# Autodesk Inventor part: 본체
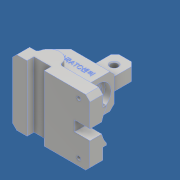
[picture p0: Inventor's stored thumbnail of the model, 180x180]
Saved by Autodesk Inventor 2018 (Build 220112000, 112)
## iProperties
Created: 2022-08
Part Number: 본체
Material: 알루미늄 6061
Document SubType Name: Modeling
Designer: home
Density: 2.7 g/cm^3
Appearance: 알루미늄 - 평지
Mass: 499.241 g
Surface Area: 337.564 cm^2
Volume: 184.904 cm^3
Author: home
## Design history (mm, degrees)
sketch "스케치1"
  geometry: L1 (63, 0)-(63, 15); L2 (-27, 15)-(-27, 0); L3 (63, 15)-(13, 15); L4 (-13, 15)-(-27, 15); L5 (10, 0)-(10, 8); L6 (10, 8)-(-10, 8); L7 (-10, 8)-(-10, 0); L8 (-27, 0)-(-10, 0); L9 (10, 0)-(63, 0); A1 r 13 centre (0, 15) between (13, 15) and (-13, 15); 2 further points
  constraints: 18 end point, 8 parallel, 2 horizontal, 2 perpendicular, 2 point on circle, 2 vertical alignment, 1 centre point, 1 midpoint
  dimensions: "d0" = 15 distance of L2.start L2.end; "d1" = 27 distance from line of L2 point (0, 0); "d2" = 90 distance of L2.end L1.start; "d3" = 26 diameter of A1; "d4" = 8 distance of L6.end L7.end; "d5" = 20 distance of L5.end L6.end; "d6" = 53 distance between parallel lines of L1 L5; "d7" = 15 distance between parallel lines of L3 L9; "d8" = 15 distance from line of point (0, 0) L3; "d9" = 50 distance from line of L3.end L1
extrude "돌출1" new body sketch "스케치1" stored distance "d10" = 76; taper "d11" = 0 deg
sketch "스케치2"
  geometry: L1 (-27, 0)-(-27, 15) reference; L2 (-27, 15)-(-13, 15) reference; L3 (13, 15)-(63, 15) reference; L4 (63, 15)-(63, 0) reference; L5 (63, 0)-(10, 0) reference; L6 (10, 0)-(10, 8) reference; L7 (10, 8)-(-10, 8) reference; L8 (-10, 8)-(-10, 0) reference; L9 (-10, 0)-(-27, 0) reference; L10 (-27, 0)-(-27, 15) reference; L11 (-27, 15)-(31, 15); L12 (31, 15)-(31, 60); L13 (31, 60)-(-27, 60); L14 (-27, 60)-(-27, 15); L15 (13, 15)-(63, 15) reference; L16 (63, 15)-(31, 15); L17 (31, 15)-(31, 19); L18 (31, 19)-(63, 19); L19 (63, 19)-(63, 15); A1 r 13 centre (0, 15) between (13, 15) and (-13, 15) reference; 1 further point
  constraints: 16 end point, 3 parallel, 2 horizontal, 1 perpendicular, 1 point on line
  dimensions: "d13" = 45 distance of L13.end L1.end; "d15" = 32 distance between parallel lines of L12 L4; "d16" = 19 distance between parallel lines of L18 L5; "d65" = 90 deg angle of L3 L14
extrude "돌출2" join sketch "스케치2" stored distance "d17" = 40; taper "d18" = 0 deg
chamfer "모따기1" distance "d19" = 18; stored, may be unused: second distance "d20" = 2, angle "d21" = 45 deg
sketch "스케치3"
  geometry: L1 (-9, 60)-(-27, 42) reference; L2 (-9, 60)-(31, 60) reference; L3 (31, 60)-(31, 19) reference; L4 (31, 19)-(63, 19) reference; L5 (63, 19)-(63, 15) reference; L6 (13, 15)-(63, 15) reference; L7 (-27, 15)-(-13, 15) reference; L8 (-27, 15)-(-27, 42) reference; L9 (2, 60)-(26, 60); L10 (26, 60)-(26, 85); L11 (21, 90)-(7, 90); L12 (2, 85)-(2, 60); L13 (2, 85)-(7, 90); L14 (21, 90)-(26, 85); A1 r 13 centre (0, 15) between (13, 15) and (-13, 15) reference; 3 further points
  constraints: 12 end point, 5 point on line, 2 parallel, 1 horizontal, 1 perpendicular
  dimensions: "d22" = 5 distance between parallel lines of L10 L3; "d23" = 24 distance of point (26, 90) point (2, 90); "d24" = 30 distance of point (2, 90) L9.start; "d25" = 5 distance of L12.start point (2, 90); "d26" = 5 distance of L11.end point (2, 90) (= d25); "d27" = 5 distance of L11.start point (26, 90) (= d25); "d28" = 5 distance of L10.end point (26, 90) (= d27)
extrude "돌출3" join sketch "스케치3" stored distance "d31" = 15; taper "d32" = 0 deg
chamfer "모따기2" distance "d33" = 5; stored, may be unused: second distance "d34" = 2, angle "d35" = 45 deg
sketch "스케치4"
  geometry: L1 (35, 41)-(40, 36) reference; L2 (35, 41)-(5, 41) reference; L3 (0, 36)-(5, 41) reference; L4 (0, 0)-(0, 36) reference; L5 (0, 0)-(40, 0) reference; L6 (40, 36)-(40, 0) reference; L7 (-18, -19)-(58, -19) reference; 3 further points
  constraints: 1 midpoint, 1 vertical alignment
  dimensions: "d36" = 42 distance from line of point (20, 23) L7
hole "구멍1" sketch "스케치4" at (20, 23) diameter "d37" = 20; stored, may be unused: countersink angle "d41" = 90 deg, drill point angle "d43" = 118 deg; dims "d38" = 6, "d39" = 29, "d40" = 7, "d42" = 8
sketch "스케치5"
  geometry: L1 (0, 0)-(-76, 0) reference; L2 (-44, 0)-(-32, 0); L3 (-32, 0)-(-32, 13.627); L4 (-44, 13.627)-(-44, 0); L5 (-76, 0)-(0, 0) reference; L6 (0, 15)-(0, 0) reference; L7 (-18, 15)-(0, 15) reference; L8 (-18, 19)-(-18, 15) reference; L9 (-18, 19)-(-58, 19) reference; L10 (-58, 15)-(-58, 19) reference; L11 (-76, 15)-(-58, 15) reference; L12 (-76, 0)-(-76, 15) reference; L13 (-55.664, 19)-(-20.336, 19); C1 r 14.5 at (-38, 42) reference; C2 r 10 at (-38, 42) reference; A1 r 29 centre (-38, 42) between (-55.664, 19) and (-44, 13.627); A2 r 29 centre (-38, 42) between (-32, 13.627) and (-20.336, 19); 3 further points
  constraints: 8 end point, 4 point on circle, 3 point on line, 2 centre point, 1 coincident, 1 horizontal, 1 midpoint, 1 parallel, 1 perpendicular, 1 vertical alignment
  dimensions: "d45" = 12 distance between parallel lines of L3 L4; "d66" = 29 radius of A2; "d67" = 29 radius of A1; "d68" = 32 distance between parallel lines of L6 L3; "d69" = 16.34201 distance from line of point (-38, 16.342) L1
extrude "돌출4" cut sketch "스케치5" distance "d46" = 18; taper "d47" = 0 deg
chamfer "모따기3" distance "d48" = 5; stored, may be unused: second distance "d49" = 2, angle "d50" = 45 deg
sketch "스케치6"
  geometry: L1 (26, 60)-(26, 85) reference; L2 (10, 0)-(58, 0) reference; C1 r 4 at (14, 77); 1 further point
  constraints: 1 centre point
  dimensions: "d51" = 8 diameter of C1; "d52" = 12 distance from line of C1.centre L1; "d53" = 77 distance from line of L2 C1.centre
extrude "돌출5" cut sketch "스케치6" extent not by distance; stored distance "d54" = 18; taper "d55" = 0 deg
sketch "스케치7"
  geometry: L1 (50, -13)-(50, 0) reference; L2 (-40, 10)-(-40, 30) reference; L3 (11, 10)-(11, 30) reference; L4 (32, 2.336)-(32, 37.664) reference; L5 (45, -18)-(0, -18) reference; A1 r 10 centre (-40, 20) between (-40, 10) and (-40, 30) reference; 2 further points
  dimensions: "d56" = 13 distance from line of point (37, -10) L1; "d57" = 8 distance from line of point (37, -10) L5
hole "구멍2" sketch "스케치7" at (37, -10) diameter "d58" = 4.5; stored, may be unused: countersink angle "d62" = 90 deg, drill point angle "d64" = 118 deg; dims "d59" = 6, "d60" = 8, "d61" = 4.4, "d63" = 8
sketch "스케치8"
  geometry: L1 (31, 60)-(-9, 60) reference; L2 (31, 19)-(31, 55) reference; 2 further points
  constraints: 1 other
  dimensions: "d70" = 18 distance from line of point (5, 42) L1; "d71" = 26 distance from line of L2 point (5, 42)
feature "엠보싱1" sketch "스케치8" dims "d72" = 0.5, "d73" = 0
fillet "모깎기1" dims "d74" = 3
chamfer "모따기4" distance "d75" = 1; stored, may be unused: second distance "d76" = 2, angle "d77" = 45 deg
node "솔리드1"
mirror "미러1"
node "투영된 루프1"
node "투영된 루프2"
node "투영된 루프3"
node "투영된 루프4"
node "투영된 루프5"
node "투영된 루프6"
other parameters: "d44" = 58
